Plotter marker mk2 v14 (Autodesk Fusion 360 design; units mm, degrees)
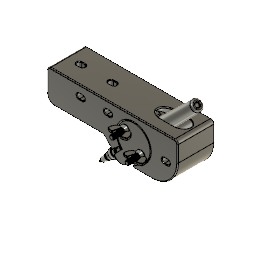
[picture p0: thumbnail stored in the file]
sketch "Profile" plane through (0, 0, 0) normal (0, 1, 0) x axis (1, 0, 0)
  line L1 (0, -79) -> (0, 0)
  line L2 (-3.4199, -80) -> (-2.4, -80)
  line L3 (-5.9916, -0.6736) -> (-5.0198, -78.42)
  line L4 (0, 0) -> (-5.4905, 0)
  line L5 (0, 30) -> (0, 0)
  line L6 (-3.2793, 30) -> (0, 30)
  line L7 (0, 43) -> (0, 30)
  line L8 (-1.5525, 43) -> (0, 43)
  line L9 (-3, 30) -> (-3, 33.8892)
  line L10 (0, 47) -> (0, 43)
  line L11 (-0.0315, 47) -> (0, 47)
  line L12 (-0.9403, 45.2389) -> (-0.6136, 46.5455)
  line L13 (-1, 43) -> (-1, 44.7538)
  line L14 (-2.8891, 34.5) -> (-2.8891, 34.9985)
  line L15 (-2.9444, 34.5) -> (-2.8891, 34.5)
  line L16 (-2.8332, 35) -> (-2.8332, 35.5014)
  line L17 (-2.8891, 34.9985) -> (-2.8332, 35)
  line L18 (-2.7778, 35.5) -> (-2.7778, 36.0001)
  line L19 (-2.8332, 35.5014) -> (-2.7778, 35.5)
  line L20 (-2.7778, 36.0001) -> (-2.0494, 42.5552)
  line L21 (-2.9878, 34.1101) -> (-2.9444, 34.5)
  line L22 (-5.019, 24.8) -> (-4.95, 24.8)
  line L23 (-4.95, 23.3) -> (-5.1672, 23.3)
  line L24 (-4.9, 24.75) -> (-4.9, 23.35)
  line L25 (-5.3, 23.3) -> (-4.9, 24.8)
  line L26 (-4.9, 23.3) -> (-5.3, 24.8)
  line L27 (-5.15, 17.3) -> (-5.2995, 17.3)
  line L28 (-5.1, 18.75) -> (-5.1, 17.35)
  line L29 (-5.2995, 18.8) -> (-5.15, 18.8)
  line L30 (-5.15, 11.3) -> (-5.2995, 11.3)
  line L31 (-5.1, 12.75) -> (-5.1, 11.35)
  line L32 (-5.2995, 12.8) -> (-5.15, 12.8)
  line L33 (-5.1, 6.75) -> (-5.1, 5.35)
  line L34 (-5.2995, 6.8) -> (-5.15, 6.8)
  line L35 (-5.15, 5.3) -> (-5.2995, 5.3)
  line L36 (-5.2995, 2.517) -> (-5.2995, 0)
  line L37 (-5.2995, 5.3) -> (-5.2995, 3.517)
  line L38 (-5.2995, 11.3) -> (-5.2995, 6.8)
  line L39 (-5.2995, 17.3) -> (-5.2995, 12.8)
  line L40 (-5.2995, 20) -> (-5.2995, 18.8)
  line L41 (-5.9601, -0.5634) -> (-5.659, -0.0923)
  line L42 (-2, -79.4) -> (-2, -79.6)
  line L43 (0, -79) -> (-1.6, -79)
  arc A1 centre (-5.2995, 3.017) radius 0.5 clockwise from (-5.2995, 2.517) to (-5.2995, 3.517)
  arc A2 centre (35.9066, 20) radius 41.2061 clockwise from (-5.019, 24.8) to (-4.2539, 29.2238)
  arc A3 centre (35.9066, 20) radius 41.2061 clockwise from (-5.2995, 20) to (-5.1672, 23.3)
  arc A4 centre (-0.0315, 46.4) radius 0.6 clockwise from (-0.6136, 46.5455) to (-0.0315, 47)
  arc A5 centre (1, 44.7538) radius 2 clockwise from (-1, 44.7538) to (-0.9403, 45.2389)
  arc A6 centre (-1.5525, 42.5) radius 0.5 clockwise from (-2.0494, 42.5552) to (-1.5525, 43)
  arc A7 centre (-1, 33.8892) radius 2 clockwise from (-3, 33.8892) to (-2.9878, 34.1101)
  arc A8 centre (-3.2793, 29) radius 1 clockwise from (-4.2539, 29.2238) to (-3.2793, 30)
  arc A9 centre (-5.4905, -0.2) radius 0.2 clockwise from (-5.659, -0.0923) to (-5.4905, 0)
  arc A10 centre (-5.7916, -0.6711) radius 0.2 clockwise from (-5.9916, -0.6736) to (-5.9601, -0.5634)
  arc A11 centre (-5.15, 18.75) radius 0.05 clockwise from (-5.15, 18.8) to (-5.1, 18.75)
  arc A12 centre (-5.15, 17.35) radius 0.05 clockwise from (-5.1, 17.35) to (-5.15, 17.3)
  arc A13 centre (-5.15, 12.75) radius 0.05 clockwise from (-5.15, 12.8) to (-5.1, 12.75)
  arc A14 centre (-5.15, 11.35) radius 0.05 clockwise from (-5.1, 11.35) to (-5.15, 11.3)
  arc A15 centre (-5.15, 6.75) radius 0.05 clockwise from (-5.15, 6.8) to (-5.1, 6.75)
  arc A16 centre (-5.15, 5.35) radius 0.05 clockwise from (-5.1, 5.35) to (-5.15, 5.3)
  arc A17 centre (-4.95, 23.35) radius 0.05 clockwise from (-4.9, 23.35) to (-4.95, 23.3)
  arc A18 centre (-4.95, 24.75) radius 0.05 clockwise from (-4.95, 24.8) to (-4.9, 24.75)
  arc A19 centre (-2.4, -79.6) radius 0.4 clockwise from (-2, -79.6) to (-2.4, -80)
  arc A20 centre (-1.6, -79.4) radius 0.4 clockwise from (-2, -79.4) to (-1.6, -79)
  arc A21 centre (-3.4199, -78.4) radius 1.6 clockwise from (-3.4199, -80) to (-5.0198, -78.42)
  point P1 (0, 0)
  point P2 (0, 0)
  point P3 (0, 0)
  point P4 (0, 0)
  point P6 (-5.2995, 0)
  point P10 (-3, 30)
  point P13 (-2.8891, 34.9985)
  point P15 (-2.9444, 34.5)
  point P16 (-2.8332, 35.5014)
  point P20 (-5.2995, 3.017)
  point P12 (-1, 43)
  point P21 (-4.9, 24.8)
  point P22 (-5.3, 24.8)
  point P23 (-5.3, 23.3)
  coincident P1 P2
  vertical L1
  perpendicular L1 L2
  coincident P1 P3
  perpendicular L1 L4
  coincident P1 P4
  perpendicular L4 L5
  perpendicular L5 L6
  coincident L4 P6
  perpendicular L4 L36
  tangent L36 A2
  perpendicular L6 L7
  perpendicular L7 L8
  coincident L6 P10
  perpendicular L6 L9
  perpendicular L8 L10
  perpendicular L10 L11
  perpendicular L8 L13
  coincident P13 L20
  vertical L14
  coincident P15 L20
  perpendicular L14 L15
  coincident P16 L20
  vertical L16
  vertical L18
  collinear L20 L21
  coincident P20 L36
  parallel L22 L23
  horizontal L22
  parallel L27 L29
  horizontal L29
  parallel L30 L32
  horizontal L32
  parallel L34 L35
  horizontal L34
  collinear L36 L37
  collinear L37 L38
  collinear L38 L39
  collinear L39 L40
  concentric A2 A3
  tangent L11 A4
  tangent L12 A4
  tangent L12 A5
  tangent L13 A5
  coincident L8 P12
  tangent L8 A6
  tangent L20 A6
  tangent L9 A7
  tangent L21 A7
  tangent L6 A8
  tangent A2 A8
  tangent L41 A9
  tangent L4 A9
  tangent L41 A10
  tangent L3 A10
  tangent L28 A11
  tangent L29 A11
  tangent L27 A12
  tangent L28 A12
  equal A11 A12
  tangent L31 A13
  tangent L32 A13
  equal A11 A13
  tangent L30 A14
  tangent L31 A14
  equal A11 A14
  tangent L33 A15
  tangent L34 A15
  equal A11 A15
  tangent L33 A16
  tangent L35 A16
  equal A11 A16
  tangent L23 A17
  tangent L24 A17
  equal A11 A17
  coincident P21 L24
  coincident P21 L22
  tangent L24 A18
  tangent L22 A18
  vertical L42
  horizontal L43
  tangent L42 A19
  tangent L2 A19
  tangent L42 A20
  tangent L43 A20
  equal A19 A20
  tangent L2 A21
  tangent L3 A21
  dimension "d1" diameter A1 = 1
  dimension "d2" distance P21 P22 = 0.4
  dimension "d3" distance P22 P23 = 1.5
  dimension "d10" radius A4 = 0.6
  dimension "d11" radius A5 = 2
  dimension "d12" radius A6 = 0.5
  dimension "d13" radius A7 = 2
  dimension "d14" radius A8 = 1
  dimension "d15" radius A9 = 0.2
  dimension "d16" radius A10 = 0.2
  dimension "d17" radius A11 = 0.05
  dimension "d18" radius A18 = 0.05
  dimension "d19" radius A19 = 0.4
  dimension "d20" radius A21 = 1.6
revolve "Revolve1" sketch "Profile" AlongAngle 360 bodies "Pen"
revolve "Revolve2" sketch "Profile" AlongAngle 360
revolve "Revolve3" sketch "Profile" AlongAngle 360
revolve "Revolve4" sketch "Profile" AlongAngle 360
position "Position1"
sketch "Pivot" plane through (0, 0, 0) normal (0, 1, 0) x axis (1, 0, 0)
  line L1 (-18.0839, -2.0119) -> (0, -21)
  line L2 (-12.2021, 3.5899) -> (-18.0839, -2.0119)
  line L3 (7.6099, -8.0737) -> (-12.2021, 3.5899)
  line L4 (-16.6832, -36.8888) -> (0, -21)
  line L5 (17.1243, -4.6911) -> (-16.6832, -36.8888)
  line L6 (5.0571, -40.085) -> (-20.2134, -13.5509)
  line L7 (-21.7341, 15.5958) -> (18.5905, -26.745)
  circle C1 centre (0, -21) radius 15
  circle C2 centre (-6.8793, -27.5517) radius 2.25
  circle C3 centre (6.8793, -14.4483) radius 2.25
  point P2 (0, -21)
  point P3 (0, -21)
  point P6 (7.6099, -8.0737)
  point P7 (0, -21)
  point P14 (-10.8621, -31.3448)
  point P15 (6.8793, -14.4483)
  point P16 (10.8621, -10.6552)
  point P17 (-6.8793, -27.5517)
  point P18 (-6.8793, -27.5517)
  point P19 (6.8793, -14.4483)
  coincident P2 P3
  perpendicular L1 L2
  coincident C1 P6
  tangent C1 L3
  coincident P2 P7
  perpendicular L1 L4
  perpendicular L1 L5
  perpendicular L5 L6
  perpendicular L5 L7
  coincident C1 P14
  coincident L4 P14
  coincident L5 P15
  coincident L7 P15
  coincident C1 P16
  coincident L5 P16
  coincident L6 P17
  coincident L4 P17
  coincident P17 P18
  coincident P15 P19
  dimension "d4" diameter C1 = 30
  dimension "d111" distance L7 P16 = 5.5
  dimension "d112" distance L6 P14 = 5.5
  dimension "d113" diameter C3 = 4.5
  dimension "d114" diameter C2 = 4.5
sketch "Hole" plane through (0, 0, 0) normal (0, 1, 0) x axis (1, 0, 0)
  line L1 (-24, -1) -> (0, -21)
  line L2 (-16, 7) -> (-24, -1)
  line L3 (8.0925, -8.0153) -> (-16, 7)
  circle C1 centre (0, -21) radius 15.3
  circle C2 centre (0, -21) radius 9.2195
  point P2 (0, -21)
  point P3 (0, -21)
  point P4 (0, -21)
  point P7 (8.0925, -8.0153)
  coincident P2 P3
  coincident P3 P4
  coincident C1 P7
  tangent C1 L3
  concentric C1 C2
  dimension "d5" diameter C1 = 30.6
sketch "Body" plane through (0, 0, 0) normal (0, 1, 0) x axis (1, 0, 0)
  line L1 (-15.6565, 0.0293) -> (40.2329, 0.0293)
  line L2 (-79.4695, -41.6545) -> (-79.4695, -13)
  line L3 (40.2329, -41.6545) -> (-79.4695, -41.6545)
  line L4 (40.2329, 0.0293) -> (40.2329, -41.6545)
  line L5 (-50, -30) -> (-47, -30)
  line L6 (-50, -34.5) -> (-50, -30)
  line L7 (-47, -34.5) -> (-50, -34.5)
  line L8 (-47, -30) -> (-47, -34.5)
  line L9 (-50, -34.5) -> (-47, -30)
  line L10 (-47, -34.5) -> (-50, -30)
  line L11 (-25, -30) -> (-22, -30)
  line L12 (-25, -34.5) -> (-25, -30)
  line L13 (-22, -34.5) -> (-25, -34.5)
  line L14 (-22, -30) -> (-22, -34.5)
  line L15 (-25, -34.5) -> (-22, -30)
  line L16 (-22, -34.5) -> (-25, -30)
  line L17 (28, -18) -> (31, -18)
  line L18 (31, -22.5) -> (28, -22.5)
  line L19 (28, -22.5) -> (31, -18)
  line L20 (31, -22.5) -> (28, -18)
  line L21 (-28, -13) -> (-15.6565, 0.0293)
  line L22 (-79.4695, -13) -> (-28, -13)
  circle C1 centre (-25, -32.25) radius 2.25
  circle C2 centre (-22, -32.25) radius 2.25
  circle C3 centre (-50, -32.25) radius 2.25
  circle C4 centre (-47, -32.25) radius 2.25
  arc A1 centre (28, -20.25) radius 2.25 clockwise from (28, -22.5) to (28, -18)
  arc A2 centre (31, -20.25) radius 2.25 clockwise from (31, -18) to (31, -22.5)
  point P9 (-48.5, -32.25)
  point P14 (-23.5, -32.25)
  point P11 (-25, -30)
  point P12 (-25, -34.5)
  point P10 (-22, -30)
  point P13 (-22, -34.5)
  point P6 (-50, -30)
  point P7 (-50, -34.5)
  point P5 (-47, -30)
  point P8 (-47, -34.5)
  point P23 (29.5, -20.25)
  point P19 (31, -18)
  point P20 (28, -18)
  point P22 (31, -22.5)
  horizontal L1
  vertical L2
  horizontal L3
  vertical L4
  perpendicular L5 L6
  parallel L5 L7
  parallel L6 L8
  horizontal L5
  coincident L9 P9
  coincident L10 P9
  perpendicular L11 L12
  parallel L11 L13
  parallel L12 L14
  horizontal L11
  coincident L15 P14
  coincident L16 P14
  coincident P11 C1
  tangent L11 C1
  coincident P12 C1
  coincident P10 C2
  tangent L11 C2
  coincident P13 C2
  coincident P6 C3
  tangent L5 C3
  coincident P7 C3
  coincident P5 C4
  tangent L5 C4
  coincident P8 C4
  parallel L17 L18
  horizontal L17
  coincident L19 P23
  coincident L20 P23
  tangent L17 A2
  perpendicular L2 L22
  dimension "d7" distance P10 P11 = 3
  dimension "d8" distance P5 P6 = 3
  dimension "d9" distance P6 P7 = 4.5
  dimension "d25" distance P11 P12 = 4.5
  dimension "d26" distance P19 P20 = 3
  dimension "d27" distance P19 P22 = 4.5
extrude "Extrude1" new body sketch "Body" profile of L1 L2 L3 L4 L5 L7 L11 L13 C1 C2 C3 C4 L17 L18 A1 A2 L21 L22 distance 17
sketch "Mounting holes" plane through (0, 0, -0.0293) normal (0, 0, -1) x axis (1, 0, 0)
  line L1 (40.2329, -17) -> (-15.6565, -17)
  line L2 (40.2329, 17) -> (40.2329, -17)
  line L3 (-15.6565, 17) -> (40.2329, 17)
  line L4 (-37.3897, -1.8603) -> (-34.3897, -1.8603)
  line L5 (-34.3897, 2.6397) -> (-37.3897, 2.6397)
  line L6 (-37.3897, 2.6397) -> (-34.3897, -1.8603)
  line L7 (-34.3897, 2.6397) -> (-37.3897, -1.8603)
  line L8 (-66.3897, -1.8603) -> (-63.3897, -1.8603)
  line L9 (-63.3897, 2.6397) -> (-66.3897, 2.6397)
  line L10 (-66.3897, 2.6397) -> (-63.3897, -1.8603)
  line L11 (-63.3897, 2.6397) -> (-66.3897, -1.8603)
  line L12 (-15.6565, -17) -> (-15.6565, 17)
  arc A1 centre (-63.3897, 0.3897) radius 2.25 clockwise from (-63.3897, 2.6397) to (-63.3897, -1.8603)
  arc A2 centre (-66.3897, 0.3897) radius 2.25 clockwise from (-66.3897, -1.8603) to (-66.3897, 2.6397)
  arc A3 centre (-37.3897, 0.3897) radius 2.25 clockwise from (-37.3897, -1.8603) to (-37.3897, 2.6397)
  arc A4 centre (-34.3897, 0.3897) radius 2.25 clockwise from (-34.3897, 2.6397) to (-34.3897, -1.8603)
  point P10 (-35.8897, 0.3897)
  point P15 (-64.8897, 0.3897)
  point P13 (-66.3897, 2.6397)
  point P14 (-63.3897, 2.6397)
  point P8 (-37.3897, 2.6397)
  point P9 (-34.3897, 2.6397)
  point P12 (-66.3897, -1.8603)
  point P7 (-37.3897, -1.8603)
  parallel L4 L5
  horizontal L4
  coincident L6 P10
  coincident L7 P10
  parallel L8 L9
  horizontal L8
  coincident L10 P15
  coincident L11 P15
  tangent L8 A2
  tangent L8 A1
  tangent L4 A3
  dimension "d32" distance P10 P15 = 29
  dimension "d33" distance P13 P14 = 3
  dimension "d34" distance P8 P9 = 3
  dimension "d35" distance P12 P13 = 4.5
  dimension "d36" distance P7 P8 = 4.5
extrude "Extrude2" cut sketch "Mounting holes" profile of L4 L5 L8 L9 A2 A1 A3 A4 against normal blind 70
work_plane "WorkPlane1" AlongDistance 0
sketch "Marker holes" plane through (40.9139, 0, 62.0529) normal (0.7071, 0, 0.7071) x axis (0.7071, 0, -0.7071)
  line L1 (-3.8974, 6.4435) -> (4.1026, 6.4435)
  line L2 (-3.8974, -6.5565) -> (-3.8974, 6.4435)
  line L3 (4.1026, -6.5565) -> (-3.8974, -6.5565)
  line L4 (-3.8974, -6.5565) -> (4.1026, 6.4435)
  line L5 (4.1026, -6.5565) -> (-3.8974, 6.4435)
  line L6 (4.1026, -5.1799) -> (4.1026, -6.5565)
  line L7 (4.1026, 6.4435) -> (4.1026, 5.067)
  circle C1 centre (0.1026, -0.0565) radius 6.5
  arc A1 centre (-3.8974, -0.0565) radius 6.5 clockwise from (-3.8974, -6.5565) to (-3.8974, 6.4435)
  arc A2 centre (4.1026, -0.0565) radius 6.5 clockwise from (4.1026, 6.4435) to (4.1026, -6.5565)
  point P1 (0.1026, -0.0565)
  point P2 (0.1026, -0.0565)
  point P7 (0.1026, -0.0565)
  point P10 (4.1026, -5.1799)
  point P11 (4.1026, 5.067)
  point P4 (-3.8974, 6.4435)
  point P5 (-3.8974, -6.5565)
  point P6 (4.1026, -6.5565)
  coincident P1 P2
  perpendicular L1 L2
  parallel L1 L3
  parallel L2 L6
  horizontal L1
  coincident L4 P7
  coincident L5 P7
  coincident P2 P7
  tangent L1 A2
  coincident C1 P10
  coincident C1 P11
  collinear L6 L7
  dimension "d50" diameter C1 = 13
  dimension "d54" distance P4 P5 = 13
  dimension "d55" distance P5 P6 = 8
extrude "Extrude6" cut sketch "Marker holes" profile of C1 L1 L3 A1 A2 against normal blind 140
extrude "Extrude7" new body sketch "Hole" profile of C1 L1 C2 along normal blind 13 and against normal blind 21 bodies "Hole cut"
extrude "Extrude9" add sketch "Hole" profile of C1 L1 L2 L3 against normal blind 21
extrude "Extrude10" new body sketch "Hole" profile of C2 along normal blind 30
combine "Combine2"
combine "Combine3" bodies "Hole cut"
extrude "Extrude11" new body sketch "Pivot" profile of C1 along normal blind 12.9 and against normal blind 17 bodies "Pivot base"
extrude "Extrude12" new body sketch "Pivot" profile of C1 L1 L2 L3 against normal blind 10
move "Move1"
combine "Combine4"
extrude "Extrude17" cut sketch "Pivot" profile of C2 C3 distance 60
extrude "Extrude13" cut sketch "Marker holes" profile of C1 against normal blind 140
sketch "Spring hole" plane through (-10.3279, 0, 12.3934) normal (0.6402, 0, -0.7682) x axis (0, 1, 0)
  line L1 (-6.5565, -1.8561) -> (-6.5565, -12.4372)
  line L2 (-17, -1.8561) -> (-6.5565, -1.8561)
  line L3 (-17, -12.4372) -> (-17, -1.8561)
  line L4 (-6.5565, -12.4372) -> (-17, -12.4372)
  line L5 (-6.5565, -12.4372) -> (-17, -1.8561)
  line L6 (-17, -12.4372) -> (-6.5565, -1.8561)
  circle C1 centre (-11.7782, -7.1466) radius 3
  point P4 (-17, -1.8561)
  point P6 (-17, -1.8561)
  point P2 (-6.5565, -12.4372)
  point P7 (-6.5565, -12.4372)
  point P3 (-6.5565, -1.8561)
  point P8 (-6.5565, -1.8561)
  point P5 (-17, -12.4372)
  point P9 (-17, -12.4372)
  point P10 (-11.7782, -7.1466)
  coincident P4 P6
  coincident P2 P7
  coincident P3 P8
  coincident P5 P9
  midpoint L6 P10
  dimension "d76" diameter C1 = 6
extrude "Extrude14" cut sketch "Spring hole" profile of C1 along normal blind 6 and against normal blind 17
sketch "Nut cut" plane through (0, 12.9, 0) normal (0, 1, 0) x axis (-1, 0, 0)
  line L1 (4.0019, 30.4713) -> (7.969, 31.5034)
  line L2 (2.9122, 26.5196) -> (4.0019, 30.4713)
  line L3 (5.7896, 23.6) -> (2.9122, 26.5196)
  line L4 (9.7567, 24.6322) -> (5.7896, 23.6)
  line L5 (10.8464, 28.5839) -> (9.7567, 24.6322)
  line L6 (7.969, 31.5034) -> (10.8464, 28.5839)
  line L7 (-5.5665, 18.3316) -> (-2.8599, 15.253)
  line L8 (-9.5859, 17.5268) -> (-5.5665, 18.3316)
  line L9 (-10.8987, 13.6435) -> (-9.5859, 17.5268)
  line L10 (-8.1921, 10.565) -> (-10.8987, 13.6435)
  line L11 (-4.1727, 11.3697) -> (-8.1921, 10.565)
  line L12 (-2.8599, 15.253) -> (-4.1727, 11.3697)
  circle C1 centre (0, 21) radius 15
  circle C2 centre (6.8793, 27.5517) radius 2.25
  circle C3 centre (-6.8793, 14.4483) radius 2.25
  point P2 (0, 21)
  point P3 (0, 21)
  point P4 (6.8793, 27.5517)
  point P12 (6.8793, 27.5517)
  point P5 (-6.8793, 14.4483)
  point P19 (-6.8793, 14.4483)
  coincident P2 P3
  coincident P4 P12
  coincident P5 P19
  dimension "d117" distance P12 L6 = 3.55
  dimension "d118" distance P19 L12 = 3.55
sketch "End pivot" plane through (0, 12.9, 0) normal (0, 1, 0) x axis (-1, 0, 0)
  circle C1 centre (0, 21) radius 15
  circle C2 centre (0, 21) radius 8.75
  circle C3 centre (0, 21) radius 2.25
  circle C4 centre (6.8793, 27.5517) radius 2.25
  circle C5 centre (-6.8793, 14.4483) radius 2.25
  concentric C1 C3
  dimension "d83" diameter C2 = 17.5
  dimension "d84" diameter C3 = 4.5
extrude "Extrude16" add sketch "End pivot" profile of C2 C3 C4 C5 along normal blind 7
extrude "Extrude15" cut sketch "Nut cut" profile of C2 C3 L1 L2 L3 L4 L5 L6 L7 L8 L9 L10 L11 L12 blind 3.6
fillet "Fillet4" radius 0.8
fillet "Fillet7" radius 1.5
fillet "Fillet8" radius 6
fillet "Fillet11" radius 1.5
fillet "Fillet13" radius 0.6
fillet "Fillet15" radius 0.6
fillet "Fillet16" radius 0.6
fillet "Fillet17" radius 4.5
fillet "Fillet18" radius 4.5
fillet "Fillet19" radius 0.8
fillet "Fillet20" radius 0.5
fillet "Fillet21" radius 0.5
fillet "Fillet22" radius 3
fillet "Fillet23" radius 7
fillet "Fillet24" radius 24
fillet "Fillet25" radius 0.8
extrude "Extrude18" cut sketch "Pivot" profile of C1 C2 C3 along normal blind 6.5 bodies "Pivot top"
extrude "Extrude19" add of existing geometry blind 3.5
fillet "Fillet26" radius 0.6
fillet "Fillet27" radius 0.6
base_feature "Base Feature1"
position "Position3"
position "Position4"
position "Position5"
position "Position6"
copy_paste "CopyPaste1"
base_feature "Base Feature1"
position "Position7"
position "Position8"
position "Position9"
copy_paste "CopyPaste2"
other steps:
create_component "CreateComponent1"
create_component "CreateComponent4"
create_component "CreateComponent5"
named bodies: "Pen", "Block", "Hole cut", "Pivot base", "Pivot top"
